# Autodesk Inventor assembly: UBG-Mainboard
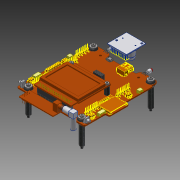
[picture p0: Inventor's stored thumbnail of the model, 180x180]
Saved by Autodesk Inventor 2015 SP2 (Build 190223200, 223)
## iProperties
Created: 2012-08
Part Number: UBG-Mainboard
Document SubType Name: Assembly
Designer: rYan
Mass: 116.991 g
Surface Area: 591.664 cm^2
Volume: 52.0204 cm^3
Density: 2.24895 g/cm^3
Author: rYan
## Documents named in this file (15)
- D:\TIGERs GIT\Hardware\mechanik\2016\Inventor\Elektronik\UBG-Mainboard.iam
- D:\TIGERs GIT\Hardware\mechanik\2016\Inventor\Elektronik\MG-Mainboard.iam
- D:\TIGERs GIT\Hardware\mechanik\2016\Inventor\Kaufteile\Gelbuchse-Taica-S-(A) [entspannt].ipt
- D:\TIGERs GIT\Hardware\mechanik\2016\Inventor\Kaufteile\Gelbuchse-Taica-S-(B) [entspannt].ipt
- D:\TIGERs GIT\Hardware\mechanik\2016\Inventor\Kaufteile\MG-LT24.iam
- D:\TIGERs GIT\Hardware\mechanik\2016\Inventor\Kaufteile\Abstandsbolzen Typ A M3-12mm.ipt
- E:\Tigers SVN\mechanik\2016\Inventor\Kaufteile\Abstandsbolzen Typ A.ipt
- D:\TIGERs GIT\Hardware\mechanik\2016\Inventor\Inhaltscenter\de-DE\DIN 9021\DIN 9021 - 3,2.ipt
- D:\TIGERs GIT\Hardware\mechanik\2016\Inventor\Inhaltscenter\de-DE\DIN 7984\DIN 7984 - M3 x 16.ipt
- D:\TIGERs GIT\Hardware\mechanik\2016\Inventor\Kaufteile\Abstandsbolzen Typ B M3-30mm-SW6.ipt
- E:\Tigers SVN\mechanik\2016\Inventor\Kaufteile\Abstandsbolzen Typ B.ipt
- D:\TIGERs GIT\Hardware\mechanik\2016\Inventor\Elektronik\MG-Kamera.iam
- D:\TIGERs GIT\Hardware\mechanik\2016\Inventor\Kaufteile\NRF24L01-PA-LNA.ipt
- D:\TIGERs GIT\Hardware\mechanik\2016\Inventor\Kaufteile\Antenne-Klein.ipt
- D:\TIGERs GIT\Hardware\mechanik\2016\Inventor\Inhaltscenter\de-DE\DIN 7984\DIN 7984 - M3 x 6.ipt
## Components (35 placed, 12 different names)
1. MG-Mainboard:1 [sub-assembly] — Passend:1, Passend:2, Passend:5, Passend:6, Passend:7, Passend:8, Passend:9, Fluchtend:1, Fluchtend:2, Passend:10, Passend:11, Passend:12, Passend:13, Passend:16, Passend:17, Passend:18, Passend:19, Passend:22, Fluchtend:3, Passend:23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
2. MG-LT24:1 [sub-assembly] — Passend:9, Fluchtend:1, Fluchtend:2, Passend:20, Passend:21
3. Abstandsbolzen Typ A M3-12mm:1 — Passend:10, Passend:12, Passend:14
4. Abstandsbolzen Typ A M3-12mm:2 — Passend:11, Passend:13, Passend:15
5. DIN 7984 M3 x 6:1 — Passend:17, Passend:19
6. DIN 7984 M3 x 6:2 — Passend:16, Passend:18
7. DIN 7984 M3 x 6:3 — Passend:14, Passend:20
8. DIN 7984 M3 x 6:4 — Passend:15, Passend:21
9. DIN 9021 3,2:1 — Einfügen:1, Einfügen:9
10. DIN 9021 3,2:2 — Einfügen:2, Einfügen:10
11. DIN 9021 3,2:3 — Einfügen:3, Einfügen:11
12. DIN 9021 3,2:4 — Einfügen:4, Einfügen:12
13. DIN 9021 3,2:5 — Einfügen:8, Einfügen:15
14. DIN 9021 3,2:6 — Einfügen:7, Einfügen:16
15. DIN 9021 3,2:7 — Einfügen:6, Einfügen:14
16. DIN 9021 3,2:8 — Einfügen:5, Einfügen:13
17. DIN 7984 M3 x 16:1 — Einfügen:10
18. DIN 7984 M3 x 16:2 — Einfügen:9
19. DIN 7984 M3 x 16:3 — Einfügen:11
20. DIN 7984 M3 x 16:4 — Einfügen:12
21. Abstandsbolzen Typ B M3-30mm-SW6:1 — Einfügen:14
22. Abstandsbolzen Typ B M3-30mm-SW6:2 — Einfügen:13
23. Abstandsbolzen Typ B M3-30mm-SW6:3 — Einfügen:15
24. Abstandsbolzen Typ B M3-30mm-SW6:4 — Einfügen:16
25. MG-Kamera:1 [sub-assembly] — Passend:22, Fluchtend:3, Passend:23
26. NRF24L01-PA-LNA:1 — Passend:24, Passend:25, Passend:26, Einfügen:17
27. Antenne-Klein:1 — Einfügen:17, Winkel:1
28. Gelbuchse-Taica-S-(B) [entspannt]:2 — Passend:4, Passend:6, Einfügen:1
29. Gelbuchse-Taica-S-(A) [entspannt]:1 — Passend:2, Passend:4, Passend:8, Einfügen:5
30. Gelbuchse-Taica-S-(B) [entspannt]:3 — Einfügen:2
31. Gelbuchse-Taica-S-(A) [entspannt]:3 — Einfügen:6
32. Gelbuchse-Taica-S-(B) [entspannt]:1 — Passend:3, Passend:5, Einfügen:3
33. Gelbuchse-Taica-S-(A) [entspannt]:2 — Passend:1, Passend:3, Passend:7, Einfügen:8
34. Gelbuchse-Taica-S-(B) [entspannt]:4 — Einfügen:4
35. Gelbuchse-Taica-S-(A) [entspannt]:4 — Einfügen:7
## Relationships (47: Mate 26, Insert 17, Flush 3, Angle 1)
- Passend:1 [Mate]: MG-Mainboard:1 ↔ Gelbuchse-Taica-S-(A) [entspannt]:2
- Passend:2 [Mate]: MG-Mainboard:1 ↔ Gelbuchse-Taica-S-(A) [entspannt]:1
- Passend:3 [Mate]: Gelbuchse-Taica-S-(B) [entspannt]:1 ↔ Gelbuchse-Taica-S-(A) [entspannt]:2
- Passend:4 [Mate]: Gelbuchse-Taica-S-(B) [entspannt]:2 ↔ Gelbuchse-Taica-S-(A) [entspannt]:1
- Passend:5 [Mate]: MG-Mainboard:1 ↔ Gelbuchse-Taica-S-(B) [entspannt]:1
- Passend:6 [Mate]: MG-Mainboard:1 ↔ Gelbuchse-Taica-S-(B) [entspannt]:2
- Passend:7 [Mate]: MG-Mainboard:1 ↔ Gelbuchse-Taica-S-(A) [entspannt]:2
- Passend:8 [Mate]: MG-Mainboard:1 ↔ Gelbuchse-Taica-S-(A) [entspannt]:1
- Passend:9 [Mate]: MG-Mainboard:1 ↔ MG-LT24:1
- Fluchtend:1 [Flush]: MG-Mainboard:1 ↔ MG-LT24:1
- Fluchtend:2 [Flush]: MG-Mainboard:1 ↔ MG-LT24:1
- Passend:10 [Mate]: MG-Mainboard:1 ↔ Abstandsbolzen Typ A M3-12mm:1
- Passend:11 [Mate]: MG-Mainboard:1 ↔ Abstandsbolzen Typ A M3-12mm:2
- Passend:12 [Mate]: MG-Mainboard:1 ↔ Abstandsbolzen Typ A M3-12mm:1
- Passend:13 [Mate]: MG-Mainboard:1 ↔ Abstandsbolzen Typ A M3-12mm:2
- Passend:14 [Mate]: Abstandsbolzen Typ A M3-12mm:1 ↔ DIN 7984 M3 x 6:3
- Passend:15 [Mate]: Abstandsbolzen Typ A M3-12mm:2 ↔ DIN 7984 M3 x 6:4
- Passend:16 [Mate]: MG-Mainboard:1 ↔ DIN 7984 M3 x 6:2
- Passend:17 [Mate]: MG-Mainboard:1 ↔ DIN 7984 M3 x 6:1
- Passend:18 [Mate]: MG-Mainboard:1 ↔ DIN 7984 M3 x 6:2
- Passend:19 [Mate]: MG-Mainboard:1 ↔ DIN 7984 M3 x 6:1
- Passend:20 [Mate]: MG-LT24:1 ↔ DIN 7984 M3 x 6:3
- Passend:21 [Mate]: MG-LT24:1 ↔ DIN 7984 M3 x 6:4
- Einfügen:1 [Insert]: DIN 9021 3,2:1 ↔ Gelbuchse-Taica-S-(B) [entspannt]:2
- Einfügen:2 [Insert]: DIN 9021 3,2:2 ↔ Gelbuchse-Taica-S-(B) [entspannt]:3
- Einfügen:3 [Insert]: DIN 9021 3,2:3 ↔ Gelbuchse-Taica-S-(B) [entspannt]:1
- Einfügen:4 [Insert]: DIN 9021 3,2:4 ↔ Gelbuchse-Taica-S-(B) [entspannt]:4
- Einfügen:5 [Insert]: DIN 9021 3,2:8 ↔ Gelbuchse-Taica-S-(A) [entspannt]:1
- Einfügen:6 [Insert]: DIN 9021 3,2:7 ↔ Gelbuchse-Taica-S-(A) [entspannt]:3
- Einfügen:7 [Insert]: DIN 9021 3,2:6 ↔ Gelbuchse-Taica-S-(A) [entspannt]:4
- Einfügen:8 [Insert]: DIN 9021 3,2:5 ↔ Gelbuchse-Taica-S-(A) [entspannt]:2
- Einfügen:9 [Insert]: DIN 9021 3,2:1 ↔ DIN 7984 M3 x 16:2
- Einfügen:10 [Insert]: DIN 9021 3,2:2 ↔ DIN 7984 M3 x 16:1
- Einfügen:11 [Insert]: DIN 9021 3,2:3 ↔ DIN 7984 M3 x 16:3
- Einfügen:12 [Insert]: DIN 9021 3,2:4 ↔ DIN 7984 M3 x 16:4
- Einfügen:13 [Insert]: DIN 9021 3,2:8 ↔ Abstandsbolzen Typ B M3-30mm-SW6:2
- Einfügen:14 [Insert]: DIN 9021 3,2:7 ↔ Abstandsbolzen Typ B M3-30mm-SW6:1
- Einfügen:15 [Insert]: DIN 9021 3,2:5 ↔ Abstandsbolzen Typ B M3-30mm-SW6:3
- Einfügen:16 [Insert]: DIN 9021 3,2:6 ↔ Abstandsbolzen Typ B M3-30mm-SW6:4
- Passend:22 [Mate]: MG-Mainboard:1 ↔ MG-Kamera:1
- Fluchtend:3 [Flush]: MG-Mainboard:1 ↔ MG-Kamera:1
- Passend:23 [Mate]: MG-Mainboard:1 ↔ MG-Kamera:1
- Passend:24 [Mate]: MG-Mainboard:1 ↔ NRF24L01-PA-LNA:1
- Passend:25 [Mate]: MG-Mainboard:1 ↔ NRF24L01-PA-LNA:1
- Passend:26 [Mate]: MG-Mainboard:1 ↔ NRF24L01-PA-LNA:1
- Einfügen:17 [Insert]: NRF24L01-PA-LNA:1 ↔ Antenne-Klein:1
- Winkel:1 [Angle]: MG-Mainboard:1 ↔ Antenne-Klein:1
